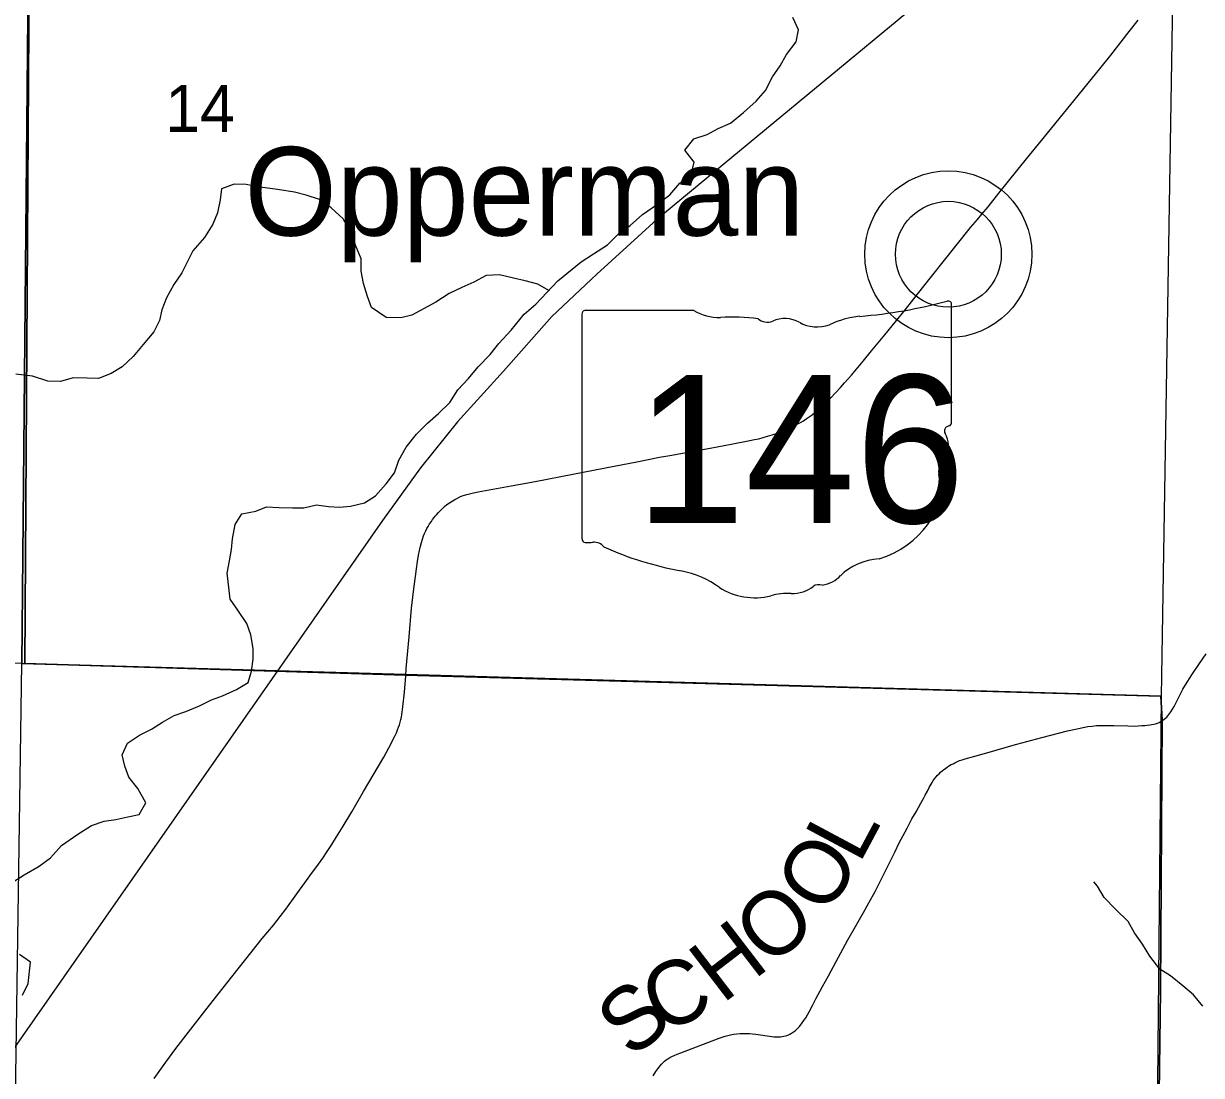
# Model space of a CAD drawing. Extents: x 0 to 34, y 0 to 22.
# Drawn here: x 3.363 to 4.413, y 18.333 to 19.271 of the extents above; entities that cross this region are included whole.
import ezdxf

# ---------------------------------------------------------------- set-up
doc = ezdxf.new("R2010")
doc.units = 0
for name, color, linetype in [('GM_X_Corporation', 7, 'Continuous'), ('GM_X_Minor_River', 7, 'Continuous'), ('GM_X_Rail_Line', 7, 'Continuous'), ('GM_X_Section_Text', 7, 'Continuous'), ('GM_X_State_Location', 7, 'Continuous'), ('GM_X_State_Route', 7, 'Continuous'), ('GM_X_State_Shield', 7, 'Continuous'), ('GM_X_Township_Road', 7, 'Continuous'), ('GM_X_Township_Road_Text', 7, 'Continuous'), ('GM_X_Unincorporated', 7, 'Continuous'), ('GM_X_Unincorporated_Location', 7, 'Continuous'), ('GM_X_Unincorporated_Text', 7, 'Continuous')]:
    doc.layers.add(name, color=color, linetype=linetype)

msp = doc.modelspace()

# ---------------------------------------------------------------- linework, layer by layer
at = {"layer": 'GM_X_Corporation'}
for points in [[(5.3543, 16.3597), (5.3699, 17.5116), (5.3717, 17.6123), (4.6401, 17.6298), (4.3705, 17.6391), (4.3669, 17.8198), (4.37, 17.9048), (4.3768, 18.4091), (4.3782, 18.6502), (4.377, 18.6713), (3.7035, 18.69), (3.3642, 18.7005), (3.3691, 19.5041), (3.3724, 19.7263), (3.3869, 20.7918), (3.3886, 20.9), (2.1, 20.9), (2.1, 15.6606)], [(3.3691, 19.5041), (3.3642, 18.7005), (3.7035, 18.69), (4.377, 18.6713), (4.3782, 18.6502), (4.3768, 18.4091), (4.37, 17.9048), (4.3669, 17.8198), (4.3705, 17.6391), (4.6401, 17.6298), (5.3717, 17.6123), (5.3798, 17.8448), (5.3967, 19.0299), (5.4062, 19.5263)]]:
    msp.add_lwpolyline(points, dxfattribs=at)
for points in [[(3.3708, 19.7265), (3.3614, 18.7006), (2.3352, 18.7231), (2.3578, 19.7506)], [(4.3939, 19.6935), (4.3772, 18.6714), (3.3614, 18.7006), (3.3708, 19.7265)], [(4.3772, 18.6714), (4.3675, 17.6365), (3.3465, 17.6805), (3.3614, 18.7006)]]:
    msp.add_lwpolyline(points, close=True, dxfattribs=at)
at = {"layer": 'GM_X_Minor_River'}
for points in [[(3.6448, 18.8398), (3.6546, 18.8406), (3.667, 18.8438), (3.6768, 18.85), (3.6862, 18.8607), (3.6936, 18.8706), (3.6977, 18.8816), (3.704, 18.8934), (3.7134, 18.9049), (3.7231, 18.9148), (3.7329, 18.9233), (3.743, 18.9332), (3.7501, 18.9443), (3.7598, 18.9546), (3.7684, 18.9649), (3.7789, 18.976), (3.7868, 18.9856), (3.7976, 18.9975), (3.8092, 19.012), (3.8197, 19.0208), (3.8392, 19.0415), (3.8602, 19.0584), (3.8711, 19.0657), (3.8835, 19.0737), (3.8937, 19.0837), (3.9038, 19.091), (3.9147, 19.1006), (3.9282, 19.1098), (3.9391, 19.1183), (3.9481, 19.1286), (3.9582, 19.1363), (3.9608, 19.1473), (3.9527, 19.1582), (3.9606, 19.1681), (3.9726, 19.172), (3.9824, 19.1775), (3.9934, 19.1821), (4.005, 19.1917), (4.0162, 19.2017), (4.0245, 19.2112), (4.0308, 19.2234), (4.0375, 19.2333), (4.0431, 19.2433), (4.0517, 19.2547), (4.0539, 19.2653), (4.0489, 19.2763)], [(3.8312, 19.033), (3.8215, 19.0386), (3.8101, 19.0415), (3.7999, 19.0441), (3.7874, 19.047), (3.7753, 19.0465), (3.7644, 19.0403), (3.7538, 19.0356), (3.7425, 19.0302), (3.7305, 19.0225), (3.7091, 19.0109), (3.6993, 19.0085), (3.6864, 19.0088), (3.6731, 19.0177), (3.6696, 19.0276), (3.6661, 19.0393), (3.6641, 19.0502), (3.664, 19.0612), (3.659, 19.0733), (3.6551, 19.0842), (3.6478, 19.097), (3.6372, 19.1068), (3.6269, 19.1142), (3.6148, 19.1179), (3.6045, 19.1205), (3.5894, 19.1229), (3.5739, 19.1251), (3.5614, 19.1276), (3.5508, 19.1278), (3.5395, 19.1236), (3.5384, 19.1137), (3.5359, 19.1023), (3.5318, 19.092), (3.5244, 19.0802), (3.5139, 19.0684), (3.5042, 19.0486), (3.4971, 19.0383), (3.4904, 19.0264), (3.4864, 19.0158), (3.4842, 19.0063), (3.479, 18.996), (3.4696, 18.9849), (3.4606, 18.9742), (3.4509, 18.965), (3.4411, 18.9589), (3.4298, 18.9546), (3.4196, 18.9549), (3.4071, 18.9551), (3.3958, 18.952), (3.3845, 18.9522), (3.3708, 18.9566), (3.3561, 18.9584)], [(3.3536, 18.506), (3.3634, 18.5121), (3.3769, 18.5199), (3.387, 18.5272), (3.3968, 18.5382), (3.4114, 18.5483), (3.4235, 18.556), (3.4348, 18.5599), (3.4453, 18.5615), (3.4559, 18.5639), (3.4661, 18.5659), (3.472, 18.5762), (3.4648, 18.589), (3.4567, 18.5991), (3.4532, 18.6089), (3.4509, 18.6191), (3.4557, 18.6294), (3.4662, 18.6367), (3.4771, 18.6421), (3.4869, 18.6483), (3.4974, 18.6541), (3.5076, 18.6576), (3.5197, 18.6627), (3.5306, 18.6681), (3.5404, 18.6716), (3.5528, 18.6774), (3.5633, 18.6836), (3.5663, 18.6938), (3.5677, 18.7045), (3.5676, 18.7139), (3.5656, 18.726), (3.5621, 18.7362), (3.5541, 18.7479), (3.5472, 18.7577), (3.546, 18.7683), (3.5444, 18.7811), (3.5465, 18.7921), (3.5483, 18.802), (3.5494, 18.8115), (3.5515, 18.8244), (3.5575, 18.8339), (3.57, 18.8363), (3.5797, 18.8402), (3.5907, 18.8396), (3.6028, 18.8393), (3.613, 18.8394), (3.6243, 18.8418), (3.6349, 18.8404), (3.6448, 18.8398)], [(4.4145, 18.3951), (4.4061, 18.4052), (4.3966, 18.4131), (4.3855, 18.4221), (4.376, 18.428), (4.3672, 18.4397), (4.3607, 18.4502), (4.3535, 18.4604), (4.3477, 18.4705), (4.3366, 18.4814), (4.3263, 18.4919), (4.3206, 18.5021), (4.3172, 18.5058)], [(3.362, 18.4049), (3.3672, 18.4152), (3.3693, 18.4342), (3.3594, 18.4412)]]:
    msp.add_lwpolyline(points, dxfattribs=at)
at = {"layer": 'GM_X_Rail_Line'}
msp.add_lwpolyline([(7.1041, 20.4576), (6.548, 20.2811), (6.4552, 20.2522), (5.6204, 20.0355), (5.1742, 19.9198), (4.9387, 19.8589), (4.9007, 19.8493), (4.8622, 19.8368), (4.8204, 19.8197), (4.7961, 19.8057), (4.7682, 19.7883), (4.6322, 19.6788), (3.9277, 19.0962), (3.874, 19.0476), (3.8339, 19.0097), (3.7908, 18.9611), (3.75, 18.9158), (3.7169, 18.8748), (3.6829, 18.8279), (3.1625, 18.0833)], dxfattribs=at)
at = {"layer": 'GM_X_State_Route'}
for points in [[(3.7037, 18.6895), (3.7042, 18.696), (3.7067, 18.7244), (3.709, 18.7498), (3.7113, 18.7695), (3.7124, 18.7781), (3.7133, 18.7848), (3.7143, 18.7915), (3.7152, 18.797), (3.716, 18.8013), (3.7169, 18.805), (3.7178, 18.8085), (3.7186, 18.8114), (3.7197, 18.8143), (3.7205, 18.8165), (3.7216, 18.8188), (3.7225, 18.8207), (3.7236, 18.8226), (3.725, 18.8249), (3.7266, 18.8272), (3.7277, 18.8288), (3.729, 18.8305), (3.73, 18.8318), (3.7311, 18.833), (3.7329, 18.8351), (3.7349, 18.8371), (3.7367, 18.8389), (3.7384, 18.8404), (3.7405, 18.8421), (3.7428, 18.8438), (3.745, 18.8453), (3.7475, 18.8468), (3.7498, 18.848), (3.752, 18.849), (3.7541, 18.8499), (3.756, 18.8506), (3.7582, 18.8512), (3.7606, 18.8518), (3.7641, 18.8526), (3.7684, 18.8534), (3.7977, 18.8588), (3.8191, 18.8627), (3.8526, 18.8692), (3.8818, 18.8748), (3.9098, 18.8803), (3.9299, 18.8843), (3.9409, 18.8863), (3.9586, 18.8896), (3.9751, 18.8924), (3.994, 18.896), (4.0105, 18.8992), (4.0146, 18.9001), (4.0185, 18.9009), (4.0225, 18.9019), (4.0263, 18.903), (4.0303, 18.9042), (4.034, 18.9055), (4.0383, 18.9072), (4.0427, 18.909), (4.0464, 18.9107), (4.0501, 18.9125), (4.0528, 18.9139), (4.0556, 18.9154), (4.0583, 18.9169), (4.0608, 18.9185), (4.0635, 18.9203), (4.0661, 18.9222), (4.0684, 18.9241), (4.071, 18.9262), (4.0771, 18.9316), (4.0828, 18.9373), (4.087, 18.9417), (4.0913, 18.9464), (4.095, 18.9506), (4.1011, 18.9576), (4.1115, 18.97), (4.1191, 18.9791), (4.131, 18.9934), (4.1494, 19.0161), (4.1601, 19.0298), (4.1724, 19.0454), (4.1829, 19.0584), (4.2074, 19.0891), (4.2134, 19.0963), (4.2174, 19.101), (4.223, 19.1076), (4.2325, 19.1198), (4.2572, 19.1502), (4.2733, 19.17), (4.2968, 19.1989), (4.3227, 19.2305), (4.3323, 19.2427), (4.3487, 19.2637), (4.3567, 19.274)], [(3.4794, 18.3306), (3.4899, 18.3452), (3.4986, 18.3572), (3.5101, 18.3719), (3.5288, 18.3959), (3.5487, 18.4213), (3.5612, 18.4369), (3.5758, 18.4553), (3.5857, 18.4673), (3.5918, 18.4751), (3.5967, 18.4815), (3.6065, 18.4951), (3.6139, 18.5051), (3.6182, 18.5112), (3.6259, 18.5217), (3.6297, 18.5271), (3.6336, 18.533), (3.6377, 18.5392), (3.642, 18.546), (3.645, 18.5508), (3.6479, 18.5555), (3.6556, 18.5683), (3.6662, 18.5865), (3.6842, 18.617), (3.6907, 18.6291), (3.6932, 18.6342), (3.6942, 18.6363), (3.6954, 18.6388), (3.6965, 18.6414), (3.6974, 18.6438), (3.6981, 18.6459), (3.6988, 18.6483), (3.6993, 18.6505), (3.6998, 18.6527), (3.7002, 18.655), (3.7006, 18.6572), (3.7012, 18.662), (3.7026, 18.6749), (3.7037, 18.6895)]]:
    msp.add_lwpolyline(points, dxfattribs=at)
at = {"layer": 'GM_X_State_Shield'}
for p, q in [((4.1904, 18.9156), (4.1904, 19.0202)), ((3.8608, 19.0118), (3.8608, 18.8117)), ((3.9606, 19.0153), (3.8641, 19.0153)), ((4.1904, 18.9156), (4.1904, 18.9156))]:
    msp.add_line(p, q, dxfattribs=at)
for centre, major_axis, start_param, end_param in [((4.073, 19.2881), (0.3495, 0), 4.814394, 5.042369), ((4.1868, 19.0207), (0.00367, 0), 6.141152, 7.989035), ((3.8646, 19.0123), (0.00382, 0), 1.712693, 3.28349), ((3.9836, 19.0385), (0.037, 0), 4.042523, 4.731795), ((3.9959, 18.9029), (0.133, 0), 1.404758, 1.657858), ((4.0417, 18.9902), (0.0222, 0), 0.950623, 2.079405), ((4.1176, 18.9542), (0.0703, 0), 1.699011, 2.107814), ((4.0261, 19.0133), (0.0107, 0), 3.836095, 5.185415), ((4.0704, 19.0219), (0.0267, 0), 4.081561, 5.145723), ((4.1865, 18.9152), (0.00393, 0), 5.05454, 6.418171), ((4.1896, 18.9079), (0.00568, 0), 1.883978, 3.671073), ((4.1535, 18.8946), (0.0341, 0), 5.934695, 6.695948), ((4.2036, 18.8718), (0.0248, 0), 2.387724, 3.262537), ((4.0926, 18.8584), (0.0874, 0), 5.101752, 6.440018), ((3.8647, 18.8113), (0.00385, 0), 3.00124, 4.508301), ((3.8652, 18.8318), (0.0294, 0), 4.665946, 4.897461), ((3.8712, 18.8002), (0.0106, 0), 0.519207, 1.627899), ((4.0051, 18.98), (0.2524, 0), 4.195997, 4.488961), ((4.1295, 18.7555), (0.0479, 0), 1.647645, 2.488434), ((3.9298, 18.7218), (0.079, 0), 0.823519, 1.323587), ((4.0688, 18.7923), (0.0282, 0), 4.937069, 5.64225), ((4.0152, 18.7992), (0.0501, 0), 4.026481, 4.996735), ((4.0479, 18.7842), (0.0267, 0), 4.691044, 5.507374), ((4.072, 18.7648), (0.00752, 0), 1.147584, 2.315152), ((4.0442, 18.73), (0.0412, 0), 1.495662, 1.94098)]:
    msp.add_ellipse(centre, major_axis=major_axis, ratio=0.8, start_param=start_param, end_param=end_param, dxfattribs=at)
at = {"layer": 'GM_X_Township_Road'}
for points in [[(4.3777, 18.6492), (4.3784, 18.6496), (4.38, 18.6508), (4.3812, 18.6518), (4.3822, 18.6528), (4.3832, 18.6538), (4.3842, 18.655), (4.3851, 18.6561), (4.386, 18.6574), (4.3875, 18.6598), (4.3887, 18.6622), (4.3929, 18.6705), (4.3967, 18.6776), (4.3989, 18.6814), (4.4045, 18.6903), (4.4114, 18.7005), (4.4174, 18.7091)], [(3.9242, 18.3331), (3.9266, 18.3369), (3.9285, 18.3393), (3.9305, 18.3418), (3.9317, 18.3433), (3.933, 18.3446), (3.9345, 18.3459), (3.936, 18.3471), (3.9375, 18.3481), (3.9392, 18.3492), (3.941, 18.3502), (3.9431, 18.3512), (3.9458, 18.3523), (3.9489, 18.3536), (3.9832, 18.3666), (3.9857, 18.3675), (3.9885, 18.3684), (3.991, 18.369), (3.9934, 18.3696), (3.9962, 18.37), (3.999, 18.3704), (4.0018, 18.3706), (4.0047, 18.3708), (4.0073, 18.3708), (4.0103, 18.3706), (4.013, 18.3704), (4.0159, 18.3701), (4.03, 18.368), (4.032, 18.3678), (4.0343, 18.3677), (4.0361, 18.3677), (4.0379, 18.3678), (4.0393, 18.3679), (4.0408, 18.3682), (4.0422, 18.3686), (4.0436, 18.369), (4.045, 18.3696), (4.0463, 18.3702), (4.0478, 18.3711), (4.0494, 18.3721), (4.0508, 18.3731), (4.0522, 18.3743), (4.0547, 18.3768), (4.0573, 18.3801), (4.0588, 18.3823), (4.0603, 18.3847), (4.0633, 18.3901), (4.0663, 18.3957), (4.0694, 18.4015), (4.0753, 18.4125), (4.0806, 18.4222), (4.0874, 18.4348), (4.0979, 18.4543), (4.1046, 18.4662), (4.1118, 18.4785), (4.1166, 18.4871), (4.1223, 18.4974), (4.1285, 18.5097), (4.1344, 18.5217), (4.1398, 18.5323), (4.1438, 18.5406), (4.1507, 18.5538), (4.155, 18.562), (4.1587, 18.5684), (4.1631, 18.5759), (4.1654, 18.5802), (4.1668, 18.583), (4.1688, 18.5868), (4.1705, 18.5899), (4.1721, 18.5928), (4.1731, 18.5945), (4.1741, 18.5961), (4.1753, 18.5978), (4.1767, 18.5996), (4.1779, 18.6009), (4.1792, 18.6023), (4.1805, 18.6035), (4.182, 18.6047), (4.1835, 18.6059), (4.185, 18.607), (4.1867, 18.6083), (4.1886, 18.6095), (4.1901, 18.6104), (4.1917, 18.6112), (4.1932, 18.612), (4.1952, 18.6129), (4.1975, 18.6139), (4.1999, 18.6147), (4.2026, 18.6156), (4.211, 18.6179), (4.2185, 18.62), (4.2259, 18.6221), (4.2433, 18.627), (4.2486, 18.6285), (4.2708, 18.6346), (4.2937, 18.6404), (4.301, 18.6421), (4.3077, 18.6435), (4.312, 18.6443), (4.3156, 18.6447), (4.3195, 18.6451), (4.3222, 18.6452), (4.3251, 18.6453), (4.3351, 18.6452), (4.3475, 18.6448), (4.3537, 18.6447), (4.3568, 18.6449), (4.36, 18.6451), (4.3628, 18.6453), (4.3647, 18.6455), (4.3672, 18.6458), (4.3689, 18.646), (4.3706, 18.6463), (4.3723, 18.6467), (4.3739, 18.6473), (4.3755, 18.648), (4.377, 18.6488), (4.3777, 18.6492)]]:
    msp.add_lwpolyline(points, dxfattribs=at)
at = {"layer": 'GM_X_Unincorporated'}
for radius in [0.0744, 0.0472]:
    msp.add_circle((4.1875, 19.0653), radius, dxfattribs=at)
at = {"layer": 'GM_X_Unincorporated_Location'}
msp.add_line((4.1875, 19.0653), (4.1875, 19.0653), dxfattribs=at)

# ---------------------------------------------------------------- texts
at = {"layer": 'GM_X_Section_Text'}
msp.add_text('14', height=0.04186, rotation=0, dxfattribs=at).set_placement((3.4892, 19.1744))
at = {"layer": 'GM_X_State_Location'}
for s in ['s', 'r']:
    msp.add_text(s, height=0.000189, dxfattribs=at).set_placement((4.0219, 18.8985))
msp.add_text('146', height=0.000189, rotation=0, dxfattribs=at).set_placement((3.9551, 18.8847))
at = {"layer": 'GM_X_State_Shield'}
msp.add_text('146', height=0.13184, dxfattribs=at).set_placement((3.9083, 18.8258))
at = {"layer": 'GM_X_Township_Road_Text'}
for s, rotation, p in [('L', 61.8733, (4.1081, 18.521)), ('O', 56.8884, (4.0781, 18.4745)), ('O', 40.1559, (4.0279, 18.4287)), ('H', 37.5198, (3.986, 18.3965)), ('C', 24.201, (3.9311, 18.3699)), ('S', 40.9834, (3.9058, 18.3472))]:
    msp.add_text(s, height=0.0568, rotation=rotation, dxfattribs=at).set_placement(p)
at = {"layer": 'GM_X_Unincorporated_Text'}
msp.add_text('Opperman', height=0.07898, rotation=0, dxfattribs=at).set_placement((3.5601, 19.0819))

doc.saveas('drawing.dxf')
